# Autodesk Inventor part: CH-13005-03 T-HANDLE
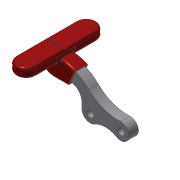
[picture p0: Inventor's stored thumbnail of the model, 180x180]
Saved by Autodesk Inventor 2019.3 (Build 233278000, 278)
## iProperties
Created: 2012-09
Part Number: CH-13005-03 T-HANDLE
Material: Ogólny
Document SubType Name: Modeling
Designer: CADENGINEERING4
Density: 1 g/cm^3
Appearance: Domyślna
Author: CADENGINEERING4
Revision Number: ÈÎºÎ
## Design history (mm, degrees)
feature "ÇÐ³ý-À­Éì1"
node "Bryła1"
